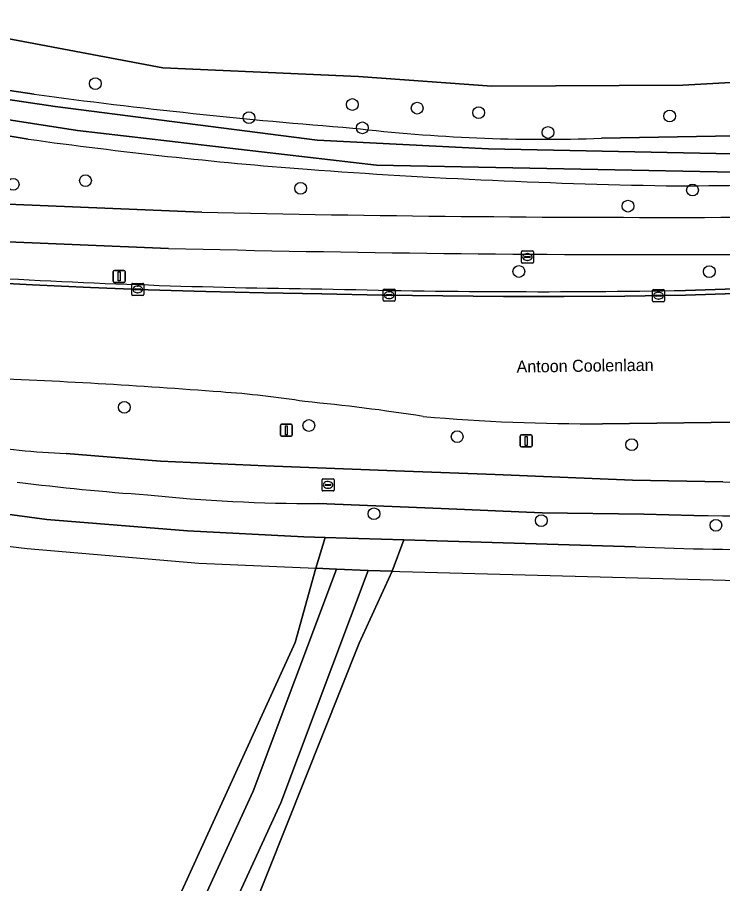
# Model space of a CAD drawing. Extents: x 160203 to 161530, y 379528 to 381797.
# Drawn here: x 160695.6 to 160754.1, y 380816.7 to 380888.6 of the extents above; entities that cross this region are included whole.
import ezdxf

# ---------------------------------------------------------------- set-up
doc = ezdxf.new("R2010")
doc.units = 0
for name, color, linetype in [('IMGEO_Berm_groen', 7, 'Continuous'), ('IMGEO_Boom', 7, 'Continuous'), ('IMGEO_Brandkraan', 7, 'Continuous'), ('IMGEO_Fietspad_open', 7, 'Continuous'), ('IMGEO_Grasland_agrarisch', 7, 'Continuous'), ('IMGEO_Groenvoorziening', 7, 'Continuous'), ('IMGEO_Hek', 7, 'Continuous'), ('IMGEO_Houtwal', 7, 'Continuous'), ('IMGEO_Kolk', 7, 'Continuous'), ('IMGEO_Lichtmast', 7, 'Continuous'), ('IMGEO_Loofbos', 7, 'Continuous'), ('IMGEO_Oever', 7, 'Continuous'), ('IMGEO_Openbare_ruimte_label', 7, 'Continuous'), ('IMGEO_Rijbaan_lokaal_gesloten', 7, 'Continuous'), ('IMGEO_Rioolput', 7, 'Continuous'), ('IMGEO_Verkeersbordpaal', 7, 'Continuous'), ('IMGEO_Voetpad_open', 7, 'Continuous'), ('IMGEO_Waterloop', 7, 'Continuous')]:
    doc.layers.add(name, color=color, linetype=linetype)

msp = doc.modelspace()

# ---------------------------------------------------------------- linework, layer by layer
at = {"layer": 'IMGEO_Berm_groen'}
for points in [[(160708.108, 380869.389), (160692.751, 380870.016), (160671.121, 380871.291), (160662.239, 380871.832), (160662.229, 380871.58), (160662.125, 380869.432)], [(160751.009, 380865.901), (160764.145, 380866.347), (160773.482, 380869.27)], [(160764.954, 380855.176), (160759.808, 380854.938), (160755.396, 380854.972), (160744.138, 380854.84)], [(160699.607, 380852.379), (160707.437, 380851.725), (160716.138, 380851.356), (160726.947, 380850.939), (160735.219, 380850.623), (160746.607, 380850.143), (160754.101, 380850.013)]]:
    msp.add_lwpolyline(points, dxfattribs=at)
for centre, radius, start, end in [((160749.557, 382539.018), 1670.143, 268.577892, 270.146024), ((160753.18, 381396.975), 528.095, 270.06877, 272.20319), ((160727.016, 381464.844), 598.844, 266.65206, 269.407261), ((160738.957, 381566.892), 701.094, 268.517729, 270.985008), ((160669.608, 380296.216), 562.888, 85.63683, 87.71052), ((160707.235, 380780.759), 76.889, 80.8812, 86.12544), ((160705.082, 380703.312), 154.034, 80.97515, 84.65853), ((160743.152, 381015.798), 160.961, 265.04302, 270.35087), ((160700.702, 380897.116), 44.75, 258.59015, 268.59817), ((160757.511, 380977.397), 127.43, 268.46675, 274.31751)]:
    msp.add_arc(centre, radius, start, end, dxfattribs=at)
at = {"layer": 'IMGEO_Boom'}
for centre in [(160702.028, 380883.068), (160723.36, 380881.333), (160728.743, 380881.033), (160733.847, 380880.656), (160714.781, 380880.24), (160749.703, 380880.376), (160724.19, 380879.394), (160739.602, 380879.011), (160701.207, 380875.013), (160695.21, 380874.707), (160719.064, 380874.376), (160751.601, 380874.231), (160746.239, 380872.899), (160737.183, 380867.473), (160752.987, 380867.463), (160704.435, 380856.202), (160719.749, 380854.689), (160732.065, 380853.763), (160746.551, 380853.099), (160725.153, 380847.365), (160739.042, 380846.799), (160753.538, 380846.409)]:
    msp.add_circle(centre, 0.489, dxfattribs=at)
at = {"layer": 'IMGEO_Brandkraan'}
for p, q in [((160720.843, 380849.333), (160720.843, 380850.185)), ((160720.918, 380850.259), (160721.77, 380850.259)), ((160721.844, 380850.185), (160721.844, 380849.333)), ((160721.102, 380849.753), (160721.102, 380849.765)), ((160721.54, 380849.716), (160721.142, 380849.716)), ((160721.145, 380849.802), (160721.543, 380849.802)), ((160721.354, 380849.479), (160721.329, 380849.479)), ((160721.331, 380850.039), (160721.356, 380850.039)), ((160721.586, 380849.765), (160721.586, 380849.753)), ((160721.77, 380849.259), (160720.918, 380849.259))]:
    msp.add_line(p, q, dxfattribs=at)
for points in [[(160720.843, 380849.333), (160720.843, 380850.185)], [(160720.918, 380850.259), (160721.77, 380850.259)], [(160721.844, 380850.185), (160721.844, 380849.333)], [(160721.77, 380849.259), (160720.918, 380849.259)]]:
    msp.add_lwpolyline(points, dxfattribs=at)
for centre, radius, start, end in [((160720.92, 380850.183), 0.0765, 91.55205, 178.44795), ((160720.92, 380850.183), 0.0765, 91.55205, 178.44795), ((160721.768, 380850.183), 0.0765, 1.55205, 88.44795), ((160721.768, 380850.183), 0.0765, 1.55205, 88.44795), ((160720.92, 380849.335), 0.0765, 181.55205, 268.44795), ((160720.92, 380849.335), 0.0765, 181.55205, 268.44795), ((160721.142, 380849.762), 0.0403, 85.87752, 175.75265), ((160721.139, 380849.752), 0.0366, 178.93798, 274.71019), ((160721.543, 380849.759), 0.043, 264.86636, 352.45326), ((160721.547, 380849.764), 0.0386, 1.73085, 96.63898), ((160721.768, 380849.335), 0.0765, 271.55205, 358.44795), ((160721.768, 380849.335), 0.0765, 271.55205, 358.44795)]:
    msp.add_arc(centre, radius, start, end, dxfattribs=at)
for centre, major_axis, ratio, start_param, end_param in [((160721.33, 380849.759), (-0.387, 0.002), 0.722429, 4.712389, 7.853982), ((160721.355, 380849.759), (-0.39, 0.002), 0.717154, 1.570796, 4.712389)]:
    msp.add_ellipse(centre, major_axis=major_axis, ratio=ratio, start_param=start_param, end_param=end_param, dxfattribs=at)
at = {"layer": 'IMGEO_Fietspad_open'}
for points in [[(160710.86, 380872.391), (160692.706, 380873.147), (160671.055, 380874.393)], [(160653.122, 380872.387), (160656.374, 380872.189), (160662.239, 380871.832), (160671.121, 380871.291), (160692.751, 380870.016), (160708.108, 380869.389)], [(160716.138, 380851.356), (160707.437, 380851.725), (160699.607, 380852.379)], [(160754.101, 380850.013), (160746.607, 380850.143), (160735.219, 380850.623), (160726.947, 380850.939), (160716.138, 380851.356)], [(160720.54, 380848.222), (160730.74, 380847.81), (160739.131, 380847.453), (160747.564, 380847.336), (160751.719, 380847.233)]]:
    msp.add_lwpolyline(points, dxfattribs=at)
for centre, radius, start, end in [((160752.767, 381397.883), 525.914, 270.12787, 274.77632), ((160749.616, 382633.843), 1761.878, 268.739565, 270.140649), ((160749.557, 382539.018), 1670.143, 268.577892, 270.146024), ((160753.18, 381396.975), 528.095, 270.06877, 272.20319), ((160700.702, 380897.116), 44.75, 258.59015, 268.59817), ((160757.511, 380977.397), 127.43, 268.46675, 274.31751), ((160719.95, 381043.695), 195.234, 262.82078, 266.00405), ((160720.106, 380981.05), 132.829, 264.05365, 270.18732), ((160758.146, 381259.181), 411.998, 269.1062, 271.73614)]:
    msp.add_arc(centre, radius, start, end, dxfattribs=at)
at = {"layer": 'IMGEO_Grasland_agrarisch'}
msp.add_lwpolyline([(160673.825, 380902.024), (160666.967, 380895.201), (160666.198, 380893.059), (160666.067, 380892.231), (160707.617, 380884.389), (160723.881, 380883.657), (160734.941, 380882.844), (160750.799, 380882.926), (160801.788, 380885.772), (160826.348, 380889.513), (160853.618, 380940.522), (160856.231, 380945.502), (160848.638, 380951.183), (160848.023, 380951.539), (160835.192, 380960.185), (160809.815, 380976.882), (160801.299, 380978.299), (160713.841, 380925.463), (160693.362, 380913.874)], close=True, dxfattribs=at)
for points in [[(160621.496, 380699.725), (160666.36, 380730.854), (160686.674, 380765.25), (160700.372, 380796.739), (160718.62, 380836.685), (160720.336, 380842.843), (160721.116, 380845.4), (160719.327, 380845.454), (160709.678, 380845.951), (160697.994, 380846.894), (160686.044, 380848.48), (160644.558, 380854.692)], [(160746.852, 380844.623), (160727.643, 380845.203), (160726.668, 380842.596), (160723.927, 380836.633), (160714.858, 380813.858), (160701.375, 380784.636), (160699.37, 380780.126), (160770.353, 380762.501), (160771.747, 380746.088), (160770.318, 380742.687), (160778.781, 380738.943), (160811.746, 380725.723), (160810.001, 380733.144), (160808.197, 380741.734), (160807.097, 380750), (160803.667, 380782.861), (160800.72, 380802.882)]]:
    msp.add_lwpolyline(points, dxfattribs=at)
msp.add_arc((160757.056, 381074.743), 230.346, 267.46117, 273.85099, dxfattribs=at)
at = {"layer": 'IMGEO_Groenvoorziening'}
for points in [[(160727.643, 380845.203), (160725.787, 380845.259), (160722.916, 380845.346), (160721.116, 380845.4), (160720.336, 380842.843), (160722.035, 380842.768), (160724.662, 380842.651), (160726.668, 380842.596)], [(160669.823, 380728.324), (160676.732, 380740.673), (160681.713, 380751.039), (160694.106, 380778.561), (160715.117, 380824.328), (160722.035, 380842.768), (160720.336, 380842.843), (160718.62, 380836.685), (160700.372, 380796.739), (160686.674, 380765.25), (160666.36, 380730.854), (160621.496, 380699.725), (160627.528, 380697.865), (160627.866, 380697.544)], [(160726.668, 380842.596), (160724.662, 380842.651), (160717.426, 380823.366), (160697.759, 380780.526), (160699.37, 380780.126), (160701.375, 380784.636), (160714.858, 380813.858), (160723.927, 380836.633)]]:
    msp.add_lwpolyline(points, close=True, dxfattribs=at)
at = {"layer": 'IMGEO_Hek'}
for points in [[(160635.899, 380853.719), (160636.693, 380853.59), (160639.112, 380853.136), (160673.536, 380847.615), (160688.052, 380845.487), (160696.377, 380844.475), (160710.618, 380843.275), (160720.336, 380842.843), (160722.035, 380842.768)], [(160724.662, 380842.651), (160726.668, 380842.596), (160727.305, 380842.579), (160755.37, 380841.813), (160764.499, 380841.725), (160790.967, 380843.218), (160797.794, 380818.979), (160800.72, 380802.882), (160803.667, 380782.861), (160807.097, 380750), (160808.197, 380741.734), (160810.001, 380733.144), (160811.746, 380725.723), (160812.287, 380716.603)], [(160697.759, 380780.526), (160717.426, 380823.366), (160724.662, 380842.651)], [(160722.035, 380842.768), (160724.662, 380842.651)]]:
    msp.add_lwpolyline(points, dxfattribs=at)
at = {"layer": 'IMGEO_Houtwal'}
msp.add_lwpolyline([(160669.823, 380728.324), (160671.915, 380726.795), (160678.954, 380739.526), (160683.987, 380750), (160697.759, 380780.526), (160717.426, 380823.366), (160724.662, 380842.651), (160722.035, 380842.768), (160715.117, 380824.328), (160694.106, 380778.561), (160681.713, 380751.039), (160676.732, 380740.673)], close=True, dxfattribs=at)
at = {"layer": 'IMGEO_Kolk'}
for p, q in [((160705.043, 380865.561), (160705.043, 380866.413)), ((160705.118, 380866.487), (160705.97, 380866.487)), ((160705.302, 380865.981), (160705.302, 380865.993)), ((160705.74, 380865.944), (160705.342, 380865.944)), ((160705.345, 380866.03), (160705.743, 380866.03)), ((160705.531, 380866.267), (160705.556, 380866.267)), ((160705.786, 380865.993), (160705.786, 380865.981)), ((160706.044, 380866.413), (160706.044, 380865.561)), ((160725.914, 380865.087), (160725.914, 380865.939)), ((160725.989, 380866.013), (160726.841, 380866.013)), ((160726.915, 380865.939), (160726.915, 380865.087)), ((160748.271, 380865.041), (160748.271, 380865.893)), ((160748.346, 380865.967), (160749.198, 380865.967)), ((160749.272, 380865.893), (160749.272, 380865.041)), ((160705.97, 380865.487), (160705.118, 380865.487)), ((160705.554, 380865.707), (160705.529, 380865.707)), ((160726.173, 380865.507), (160726.173, 380865.519)), ((160726.611, 380865.47), (160726.213, 380865.47)), ((160726.216, 380865.556), (160726.614, 380865.556)), ((160726.425, 380865.233), (160726.4, 380865.233)), ((160726.402, 380865.793), (160726.427, 380865.793)), ((160726.657, 380865.519), (160726.657, 380865.507)), ((160748.53, 380865.461), (160748.53, 380865.473)), ((160748.968, 380865.424), (160748.57, 380865.424)), ((160748.573, 380865.51), (160748.971, 380865.51)), ((160748.782, 380865.187), (160748.757, 380865.187)), ((160748.759, 380865.747), (160748.784, 380865.747)), ((160749.014, 380865.473), (160749.014, 380865.461)), ((160726.841, 380865.013), (160725.989, 380865.013)), ((160749.198, 380864.967), (160748.346, 380864.967))]:
    msp.add_line(p, q, dxfattribs=at)
for points in [[(160705.043, 380865.561), (160705.043, 380866.413)], [(160705.118, 380866.487), (160705.97, 380866.487)], [(160706.044, 380866.413), (160706.044, 380865.561)], [(160725.914, 380865.087), (160725.914, 380865.939)], [(160725.989, 380866.013), (160726.841, 380866.013)], [(160726.915, 380865.939), (160726.915, 380865.087)], [(160748.271, 380865.041), (160748.271, 380865.893)], [(160748.346, 380865.967), (160749.198, 380865.967)], [(160749.272, 380865.893), (160749.272, 380865.041)], [(160705.97, 380865.487), (160705.118, 380865.487)], [(160726.841, 380865.013), (160725.989, 380865.013)], [(160749.198, 380864.967), (160748.346, 380864.967)]]:
    msp.add_lwpolyline(points, dxfattribs=at)
for centre, radius, start, end in [((160705.12, 380866.411), 0.0765, 91.55205, 178.44795), ((160705.12, 380866.411), 0.0765, 91.55205, 178.44795), ((160705.342, 380865.99), 0.0403, 85.87752, 175.75265), ((160705.339, 380865.98), 0.0366, 178.93798, 274.71019), ((160705.743, 380865.987), 0.043, 264.86636, 352.45326), ((160705.747, 380865.992), 0.0386, 1.73085, 96.63898), ((160705.968, 380866.411), 0.0765, 1.55205, 88.44795), ((160705.968, 380866.411), 0.0765, 1.55205, 88.44795), ((160725.991, 380865.937), 0.0765, 91.55205, 178.44795), ((160725.991, 380865.937), 0.0765, 91.55205, 178.44795), ((160726.839, 380865.937), 0.0765, 1.55205, 88.44795), ((160726.839, 380865.937), 0.0765, 1.55205, 88.44795), ((160748.348, 380865.891), 0.0765, 91.55205, 178.44795), ((160748.348, 380865.891), 0.0765, 91.55205, 178.44795), ((160749.196, 380865.891), 0.0765, 1.55205, 88.44795), ((160749.196, 380865.891), 0.0765, 1.55205, 88.44795), ((160705.12, 380865.563), 0.0765, 181.55205, 268.44795), ((160705.12, 380865.563), 0.0765, 181.55205, 268.44795), ((160705.968, 380865.563), 0.0765, 271.55205, 358.44795), ((160705.968, 380865.563), 0.0765, 271.55205, 358.44795), ((160726.213, 380865.516), 0.0403, 85.87752, 175.75265), ((160726.21, 380865.506), 0.0366, 178.93798, 274.71019), ((160726.614, 380865.513), 0.043, 264.86636, 352.45326), ((160726.618, 380865.518), 0.0386, 1.73085, 96.63898), ((160748.57, 380865.47), 0.0403, 85.87752, 175.75265), ((160748.567, 380865.46), 0.0366, 178.93798, 274.71019), ((160748.971, 380865.467), 0.043, 264.86636, 352.45326), ((160748.975, 380865.472), 0.0386, 1.73085, 96.63898), ((160725.991, 380865.089), 0.0765, 181.55205, 268.44795), ((160725.991, 380865.089), 0.0765, 181.55205, 268.44795), ((160726.839, 380865.089), 0.0765, 271.55205, 358.44795), ((160726.839, 380865.089), 0.0765, 271.55205, 358.44795), ((160748.348, 380865.043), 0.0765, 181.55205, 268.44795), ((160748.348, 380865.043), 0.0765, 181.55205, 268.44795), ((160749.196, 380865.043), 0.0765, 271.55205, 358.44795), ((160749.196, 380865.043), 0.0765, 271.55205, 358.44795)]:
    msp.add_arc(centre, radius, start, end, dxfattribs=at)
for centre, major_axis, ratio, start_param, end_param in [((160705.53, 380865.987), (-0.387, 0.002), 0.722429, 4.712389, 7.853982), ((160705.555, 380865.987), (-0.39, 0.002), 0.717154, 1.570796, 4.712389), ((160726.401, 380865.513), (-0.387, 0.002), 0.722429, 4.712389, 7.853982), ((160726.426, 380865.513), (-0.39, 0.002), 0.717154, 1.570796, 4.712389), ((160748.758, 380865.467), (-0.387, 0.002), 0.722429, 4.712389, 7.853982), ((160748.783, 380865.467), (-0.39, 0.002), 0.717154, 1.570796, 4.712389)]:
    msp.add_ellipse(centre, major_axis=major_axis, ratio=ratio, start_param=start_param, end_param=end_param, dxfattribs=at)
at = {"layer": 'IMGEO_Lichtmast'}
for p, q in [((160703.511, 380866.666), (160703.511, 380867.466)), ((160703.511, 380867.466), (160703.511, 380866.666)), ((160703.611, 380867.566), (160704.401, 380867.566)), ((160704.401, 380867.566), (160703.611, 380867.566)), ((160704.501, 380867.466), (160704.501, 380866.666)), ((160704.501, 380866.666), (160704.501, 380867.466)), ((160704.401, 380866.566), (160703.611, 380866.566)), ((160703.611, 380866.566), (160704.401, 380866.566)), ((160737.292, 380853.013), (160737.292, 380853.813)), ((160737.292, 380853.813), (160737.292, 380853.013)), ((160737.392, 380853.913), (160738.182, 380853.913)), ((160738.182, 380853.913), (160737.392, 380853.913)), ((160738.282, 380853.813), (160738.282, 380853.013)), ((160738.282, 380853.013), (160738.282, 380853.813)), ((160738.182, 380852.913), (160737.392, 380852.913)), ((160737.392, 380852.913), (160738.182, 380852.913))]:
    msp.add_line(p, q, dxfattribs=at)
for points in [[(160703.931, 380867.441), (160704.081, 380867.441), (160704.081, 380866.691), (160703.931, 380866.691), (160703.931, 380867.441)], [(160737.712, 380853.788), (160737.862, 380853.788), (160737.862, 380853.038), (160737.712, 380853.038), (160737.712, 380853.788)]]:
    msp.add_lwpolyline(points, dxfattribs=at)
for centre, start, end in [((160703.611, 380867.466), 90, 180), ((160703.611, 380867.466), 90, 180), ((160704.401, 380867.466), 0, 90), ((160704.401, 380867.466), 360, 90), ((160703.611, 380866.666), 180, 270), ((160703.611, 380866.666), 180, 270), ((160704.401, 380866.666), 270, 0), ((160704.401, 380866.666), 270, 0), ((160737.392, 380853.813), 90, 180), ((160737.392, 380853.813), 90, 180), ((160738.182, 380853.813), 0, 90), ((160738.182, 380853.813), 360, 90), ((160737.392, 380853.013), 180, 270), ((160737.392, 380853.013), 180, 270), ((160738.182, 380853.013), 270, 0), ((160738.182, 380853.013), 270, 0)]:
    msp.add_arc(centre, 0.1, start, end, dxfattribs=at)
at = {"layer": 'IMGEO_Loofbos'}
for points in [[(160907.851, 381043.87), (160858.699, 380950.205), (160856.231, 380945.502), (160853.618, 380940.522), (160826.348, 380889.513), (160801.788, 380885.772), (160750.799, 380882.926), (160734.941, 380882.844), (160723.881, 380883.657), (160707.617, 380884.389), (160666.067, 380892.231), (160666.198, 380893.059), (160666.967, 380895.201), (160673.825, 380902.024), (160675.902, 380904.091), (160673.246, 380902.33), (160665.485, 380896.703), (160663.763, 380895.083), (160661.52, 380893.089)], [(160696.458, 380878.46), (160686.377, 380880.107), (160664.399, 380884.178), (160665.256, 380887.439), (160668.907, 380886.59), (160677.721, 380885.039), (160696.948, 380882.185)], [(160744.051, 380878.531), (160764.549, 380878.888)], [(160653.249, 380875.495), (160671.055, 380874.393), (160692.706, 380873.147), (160710.86, 380872.391)]]:
    msp.add_lwpolyline(points, dxfattribs=at)
for centre, radius, start, end in [((160760.784, 381357.319), 479.403, 262.34788, 265.52699), ((160739.288, 381014.967), 136.519, 263.31519, 271.99946), ((160748.861, 381254.963), 380.132, 262.07627, 265.58827), ((160758.863, 381405.664), 531.158, 265.76297, 269.08529), ((160747.338, 381334.648), 460.085, 270.37936, 273.78036), ((160752.767, 381397.883), 525.914, 270.12787, 274.77632), ((160749.616, 382633.843), 1761.878, 268.739565, 270.140649)]:
    msp.add_arc(centre, radius, start, end, dxfattribs=at)
at = {"layer": 'IMGEO_Oever'}
for points in [[(160696.948, 380882.185), (160677.721, 380885.039), (160668.907, 380886.59), (160665.256, 380887.439), (160664.399, 380884.178), (160686.377, 380880.107), (160696.458, 380878.46)], [(160825.551, 380880.037), (160807.313, 380878.499), (160804.687, 380878.277), (160790.231, 380877.058), (160762.11, 380875.592), (160725.359, 380876.304), (160700.542, 380879.176), (160664.771, 380884.735), (160665.342, 380886.123), (160698.701, 380881.165), (160720.431, 380878.382), (160734.651, 380877.662), (160757.598, 380877.195), (160785.206, 380878.553), (160804.025, 380879.559), (160807.284, 380879.846), (160818.135, 380880.801)], [(160764.549, 380878.888), (160744.051, 380878.531)]]:
    msp.add_lwpolyline(points, dxfattribs=at)
for centre, radius, start, end in [((160760.784, 381357.319), 479.403, 262.34788, 265.52699), ((160739.288, 381014.967), 136.519, 263.31519, 271.99946), ((160748.861, 381254.963), 380.132, 262.07627, 265.58827), ((160758.863, 381405.664), 531.158, 265.76297, 269.08529), ((160747.338, 381334.648), 460.085, 270.37936, 273.78036)]:
    msp.add_arc(centre, radius, start, end, dxfattribs=at)
at = {"layer": 'IMGEO_Rijbaan_lokaal_gesloten'}
for points in [[(160662.125, 380869.432), (160662.104, 380869.08), (160666.74, 380868.566), (160670.948, 380868.173), (160675.158, 380867.808), (160679.371, 380867.47), (160683.586, 380867.16), (160687.803, 380866.878), (160692.021, 380866.623), (160696.816, 380866.362), (160701.613, 380866.139), (160706.412, 380865.955), (160711.212, 380865.809), (160716.013, 380865.701), (160720.814, 380865.632), (160725.847, 380865.521), (160730.882, 380865.446), (160735.916, 380865.406), (160740.951, 380865.402), (160745.986, 380865.434), (160751.02, 380865.501), (160777.4, 380866.397)], [(160777.4, 380866.397), (160751.02, 380865.501), (160745.986, 380865.434), (160740.951, 380865.402), (160735.916, 380865.406), (160730.882, 380865.446), (160725.847, 380865.521), (160720.814, 380865.632), (160716.013, 380865.701), (160711.212, 380865.809), (160706.412, 380865.955), (160701.613, 380866.139), (160696.816, 380866.362), (160692.021, 380866.623), (160687.803, 380866.878), (160683.586, 380867.16), (160679.371, 380867.47), (160675.158, 380867.808), (160670.948, 380868.173), (160666.74, 380868.566), (160662.104, 380869.08)], [(160777.4, 380866.397), (160777.379, 380866.797), (160764.145, 380866.347), (160751.009, 380865.901)], [(160744.138, 380854.84), (160755.396, 380854.972), (160759.808, 380854.938), (160764.954, 380855.176), (160775.062, 380855.643), (160778.519, 380855.813), (160783.616, 380856.141), (160789.618, 380856.56), (160789.635, 380858.023), (160789.663, 380860.405), (160784.608, 380860.095)]]:
    msp.add_lwpolyline(points, dxfattribs=at)
for centre, radius, start, end in [((160727.016, 381464.844), 598.844, 266.65206, 269.407261), ((160738.957, 381566.892), 701.094, 268.517729, 270.985008), ((160669.608, 380296.216), 562.888, 85.63683, 87.71052), ((160707.235, 380780.759), 76.889, 80.8812, 86.12544), ((160705.082, 380703.312), 154.034, 80.97515, 84.65853), ((160743.152, 381015.798), 160.961, 265.04302, 270.35087)]:
    msp.add_arc(centre, radius, start, end, dxfattribs=at)
at = {"layer": 'IMGEO_Rioolput'}
for p, q in [((160737.391, 380868.251), (160737.391, 380869.103)), ((160737.466, 380869.177), (160738.318, 380869.177)), ((160737.879, 380868.957), (160737.904, 380868.957)), ((160738.392, 380869.103), (160738.392, 380868.251)), ((160738.318, 380868.177), (160737.466, 380868.177)), ((160737.65, 380868.671), (160737.65, 380868.683)), ((160738.088, 380868.634), (160737.69, 380868.634)), ((160737.693, 380868.72), (160738.091, 380868.72)), ((160737.902, 380868.397), (160737.877, 380868.397)), ((160738.134, 380868.683), (160738.134, 380868.671))]:
    msp.add_line(p, q, dxfattribs=at)
for points in [[(160737.391, 380868.251), (160737.391, 380869.103)], [(160737.466, 380869.177), (160738.318, 380869.177)], [(160738.392, 380869.103), (160738.392, 380868.251)], [(160738.318, 380868.177), (160737.466, 380868.177)]]:
    msp.add_lwpolyline(points, dxfattribs=at)
for centre, radius, start, end in [((160737.468, 380869.101), 0.0765, 91.55205, 178.44795), ((160737.468, 380869.101), 0.0765, 91.55205, 178.44795), ((160738.316, 380869.101), 0.0765, 1.55205, 88.44795), ((160738.316, 380869.101), 0.0765, 1.55205, 88.44795), ((160737.468, 380868.253), 0.0765, 181.55205, 268.44795), ((160737.468, 380868.253), 0.0765, 181.55205, 268.44795), ((160737.69, 380868.68), 0.0403, 85.87752, 175.75265), ((160737.687, 380868.67), 0.0366, 178.93798, 274.71019), ((160738.091, 380868.677), 0.043, 264.86636, 352.45326), ((160738.095, 380868.682), 0.0386, 1.73085, 96.63898), ((160738.316, 380868.253), 0.0765, 271.55205, 358.44795), ((160738.316, 380868.253), 0.0765, 271.55205, 358.44795)]:
    msp.add_arc(centre, radius, start, end, dxfattribs=at)
for centre, major_axis, ratio, start_param, end_param in [((160737.878, 380868.677), (-0.387, 0.002), 0.722429, 4.712389, 7.853982), ((160737.903, 380868.677), (-0.39, 0.002), 0.717154, 1.570796, 4.712389)]:
    msp.add_ellipse(centre, major_axis=major_axis, ratio=ratio, start_param=start_param, end_param=end_param, dxfattribs=at)
at = {"layer": 'IMGEO_Verkeersbordpaal'}
for p, q in [((160717.383, 380853.897), (160717.383, 380854.697)), ((160717.383, 380854.697), (160717.383, 380853.897)), ((160717.483, 380854.797), (160718.273, 380854.797)), ((160718.273, 380854.797), (160717.483, 380854.797)), ((160718.373, 380854.697), (160718.373, 380853.897)), ((160718.373, 380853.897), (160718.373, 380854.697)), ((160718.273, 380853.797), (160717.483, 380853.797)), ((160717.483, 380853.797), (160718.273, 380853.797))]:
    msp.add_line(p, q, dxfattribs=at)
msp.add_lwpolyline([(160717.803, 380854.672), (160717.953, 380854.672), (160717.953, 380853.922), (160717.803, 380853.922), (160717.803, 380854.672)], dxfattribs=at)
for centre, start, end in [((160717.483, 380854.697), 90, 180), ((160717.483, 380854.697), 90, 180), ((160718.273, 380854.697), 0, 90), ((160718.273, 380854.697), 360, 90), ((160717.483, 380853.897), 180, 270), ((160717.483, 380853.897), 180, 270), ((160718.273, 380853.897), 270, 0), ((160718.273, 380853.897), 270, 0)]:
    msp.add_arc(centre, 0.1, start, end, dxfattribs=at)
at = {"layer": 'IMGEO_Voetpad_open'}
for points in [[(160677.721, 380852.395), (160665.771, 380854.06), (160657.796, 380855.265), (160641.107, 380857.988), (160620.908, 380861.53), (160601.608, 380864.985), (160579.354, 380868.964), (160576.691, 380869.445), (160576.311, 380867.23), (160633.124, 380856.774), (160636.54, 380856.152), (160644.558, 380854.692), (160686.044, 380848.48), (160697.994, 380846.894), (160709.678, 380845.951), (160719.327, 380845.454), (160721.116, 380845.4), (160722.916, 380845.346), (160725.787, 380845.259), (160727.643, 380845.203), (160746.852, 380844.623)], [(160739.131, 380847.453), (160730.74, 380847.81), (160720.54, 380848.222)], [(160751.719, 380847.233), (160747.564, 380847.336), (160739.131, 380847.453)]]:
    msp.add_lwpolyline(points, dxfattribs=at)
for centre, radius, start, end in [((160719.95, 381043.695), 195.234, 262.82078, 266.00405), ((160720.106, 380981.05), 132.829, 264.05365, 270.18732), ((160758.146, 381259.181), 411.998, 269.1062, 271.73614), ((160757.056, 381074.743), 230.346, 267.46117, 273.85099)]:
    msp.add_arc(centre, radius, start, end, dxfattribs=at)
at = {"layer": 'IMGEO_Waterloop'}
msp.add_lwpolyline([(160818.135, 380880.801), (160807.284, 380879.846), (160804.025, 380879.559), (160785.206, 380878.553), (160757.598, 380877.195), (160734.651, 380877.662), (160720.431, 380878.382), (160698.701, 380881.165), (160665.342, 380886.123), (160664.771, 380884.735), (160700.542, 380879.176), (160725.359, 380876.304), (160762.11, 380875.592), (160790.231, 380877.058), (160804.687, 380878.277), (160807.313, 380878.499), (160825.551, 380880.037)], dxfattribs=at)

# ---------------------------------------------------------------- texts
at = {"layer": 'IMGEO_Openbare_ruimte_label'}
msp.add_text('Antoon Coolenlaan', height=1, rotation=0.7448, dxfattribs=at).set_placement((160736.998, 380859.08))

doc.saveas('drawing.dxf')
